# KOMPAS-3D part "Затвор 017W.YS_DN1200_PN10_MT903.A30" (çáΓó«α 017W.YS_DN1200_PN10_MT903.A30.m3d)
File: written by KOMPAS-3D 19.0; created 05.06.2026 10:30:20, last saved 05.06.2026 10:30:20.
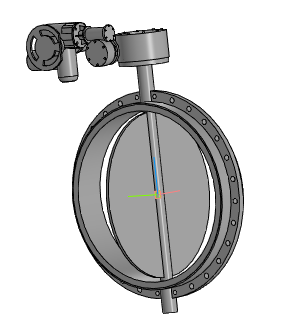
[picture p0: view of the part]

Document properties: Автор: Энергия; Полное имя файла: ..\..\..\3d для проектировщиков\x.x Тип 017W.Y(S) Затвор дисковый поворотный межфланцевый\Затвор 017W.Y(S)_DN32-DN1200_QT.A_MT903.A\Затвор 017W.YS_DN1200_PN10_MT903.A30.a3d

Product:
- Part/product: Затвор 017W.YS_DN1200_PN10_MT903.A30
    Масса: 1178.04

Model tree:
1. Операция без истории:1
